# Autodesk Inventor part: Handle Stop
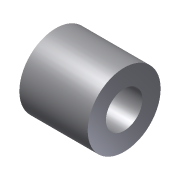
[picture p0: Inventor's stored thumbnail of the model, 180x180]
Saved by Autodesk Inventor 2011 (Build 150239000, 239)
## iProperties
Shininess: 77.0
Length Units: 11269
Angle Units: 11279
Time Units: 11290
Mass Units: 11283
Length Display Precision: 3
Angle Display Precision: 2
Compacted: True
Created: 2002-02
Part Number: Handle Stop
Document SubType Name: Modeling
Designer: ***
Density: 1 g/cm^3
Density: 0.0
Volumn: 0.0
Area: 0.0
PropertySet Name: Model Information
Control State: 0
Master: False
Checked Out: False
Author: ***
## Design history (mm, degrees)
sketch "Sketch1"
  geometry: L1 (0, 0)-(0, -2); L2 (0, -2)-(8, -2); L3 (8, -2)-(8, 13); L4 (8, 13)-(4, 13); L5 (4, 13)-(4, 0); L6 (4, 0)-(0, 0)
  constraints: 12 end point, 4 parallel, 1 perpendicular, 1 vertical
  dimensions: "d0" = 16 diameter of L3 L1; "d1" = 8 diameter of L5 L1; "d2" = 2 distance of L1.start L1.end; "d3" = 15 distance of L2.end L3.end
revolve "Revolution1" sketch "Sketch1" stored, may be unused: angle "d4" = 90 deg
body "Solid1"
